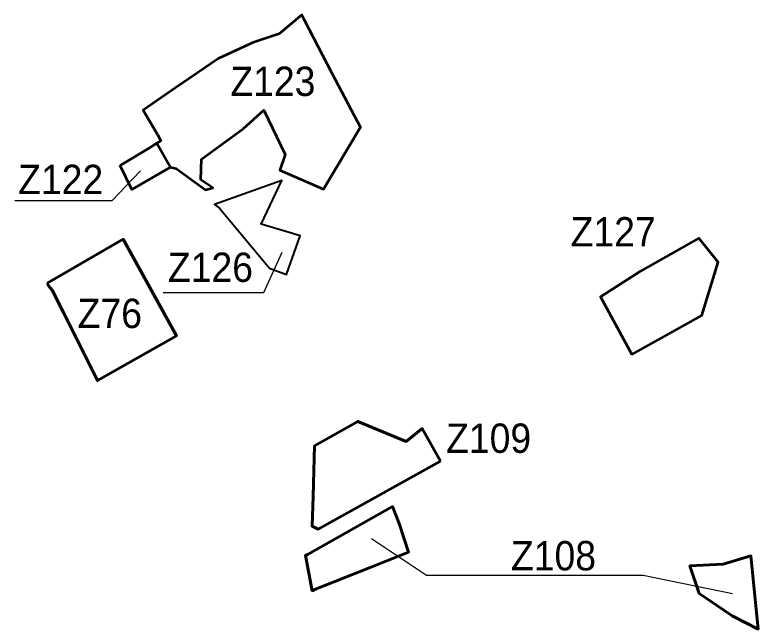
# Model space of a CAD drawing. Extents: x -650277 to -643422, y -1073980 to -1066720.
# Drawn here: x -646864 to -646257, y -1073134 to -1072632 of the extents above; entities that cross this region are included whole.
import ezdxf

# ---------------------------------------------------------------- set-up
doc = ezdxf.new("R2010")
doc.units = 0
doc.header["$LTSCALE"] = 9.6
for name, color, linetype, lineweight in [('1', 7, 'Continuous', 60), ('18', 7, 'Continuous', 60), ('34', 7, 'Continuous', 60), ('35', 7, 'Continuous', 60), ('63', 7, 'Continuous', 25)]:
    doc.layers.add(name, color=color, linetype=linetype, lineweight=lineweight)

msp = doc.modelspace()

# ---------------------------------------------------------------- linework, layer by layer
at = {"layer": '1', "lineweight": 53}
for points in [[(-646737.05, -1072756.4), (-646732.5, -1072757.63), (-646708.65, -1072775.02), (-646702.45, -1072773.39), (-646712.46, -1072766.76), (-646711.79, -1072750.02), (-646677.39, -1072724.85), (-646660.89, -1072709.97), (-646643.36, -1072746.04), (-646647.93, -1072759.01), (-646612.11, -1072774.56), (-646581.92, -1072723.91), (-646589.37, -1072709.83), (-646605.23, -1072679.37), (-646627.32, -1072636.95), (-646629.86, -1072632.07), (-646648.27, -1072647.48), (-646669.6, -1072654.53), (-646697.89, -1072667.65)], [(-646697.89, -1072667.65), (-646732.95, -1072691.68), (-646759.491, -1072709.878), (-646757.5, -1072713.3), (-646747.87, -1072729.85), (-646744.94, -1072734.88), (-646748.3, -1072737.01), (-646737.05, -1072756.4)]]:
    msp.add_lwpolyline(points, dxfattribs=at)
for points in [[(-646778.2, -1072755.19), (-646755.1, -1072741.28), (-646748.3, -1072737.01), (-646737.05, -1072756.4), (-646768.74, -1072774.78)], [(-646360.22, -1072909.57), (-646303.02, -1072877.74), (-646289.63, -1072834.04), (-646305.56, -1072814.43), (-646353.25, -1072841.63), (-646385.86, -1072862.59)]]:
    msp.add_lwpolyline(points, close=True, dxfattribs=at)
at = {"layer": '1', "lineweight": 25}
for points in [[(-646864.278, -1072783.783), (-646784.878, -1072783.783), (-646761.687, -1072759.411)], [(-646743, -1072859), (-646661, -1072859), (-646646, -1072826)]]:
    msp.add_lwpolyline(points, dxfattribs=at)
at = {"layer": '1', "lineweight": 40}
for points in [[(-646653.02, -1072806.07), (-646663.07, -1072803.04), (-646663.07, -1072803.04), (-646646.12, -1072767.32), (-646646.31, -1072767.388), (-646701.12, -1072787.08), (-646697.09, -1072790.03), (-646656.36, -1072839.08)], [(-646656.36, -1072839.08), (-646642.404, -1072844.195), (-646631.08, -1072812.68), (-646643.01, -1072809.08), (-646651.11, -1072806.64), (-646653.02, -1072806.07)]]:
    msp.add_lwpolyline(points, dxfattribs=at)
at = {"layer": '18'}
msp.add_lwpolyline([(-646837.81, -1072851.3), (-646836.5, -1072853.76), (-646833.67, -1072857.15), (-646824.89, -1072874.66), (-646796.68, -1072930.92), (-646732.28, -1072894.29), (-646775.85, -1072815.39), (-646834.08, -1072849.15)], close=True, dxfattribs=at)
at = {"layer": '34'}
for points in [[(-646574.156, -1073083.691), (-646542.62, -1073071.1), (-646550.01, -1073048.55), (-646552.79, -1073041.53), (-646555.79, -1073033.92), (-646624.69, -1073072.66), (-646626.967, -1073073.918), (-646621.38, -1073102.66), (-646620.19, -1073102.14), (-646618.56, -1073101.42)], [(-646298.029, -1073109.723), (-646278.38, -1073123.25), (-646257.09, -1073134.01), (-646262.94, -1073074.15), (-646285.77, -1073081.01), (-646312.87, -1073082.4), (-646305.18, -1073104.8)]]:
    msp.add_lwpolyline(points, close=True, dxfattribs=at)
at = {"layer": '35'}
msp.add_lwpolyline([(-646516.7, -1072996.65), (-646531.46, -1072970.12), (-646544.68, -1072980.62), (-646584.23, -1072964.22), (-646619.48, -1072984.34), (-646620.71, -1073025.49), (-646621.44, -1073049.79), (-646616.55, -1073052.21)], close=True, dxfattribs=at)
at = {"layer": '63'}
msp.add_lwpolyline([(-646573, -1073060), (-646528, -1073090), (-646351, -1073090), (-646278, -1073105)], dxfattribs=at)

# ---------------------------------------------------------------- texts
at = {"layer": '1', "width": 0.95}
for s, p in [('Z123', (-646688.261, -1072698.34)), ('Z122', (-646861.605, -1072778.534)), ('Z127', (-646410.261, -1072821.34)), ('Z126', (-646739.261, -1072850.34))]:
    msp.add_text(s, height=24, dxfattribs=at).set_placement(p)
at = {"layer": '63', "width": 0.95}
for s, p in [('Z76', (-646813, -1072888)), ('Z109', (-646512, -1072990)), ('Z108', (-646459, -1073086))]:
    msp.add_text(s, height=24, dxfattribs=at).set_placement(p)

doc.saveas('drawing.dxf')
